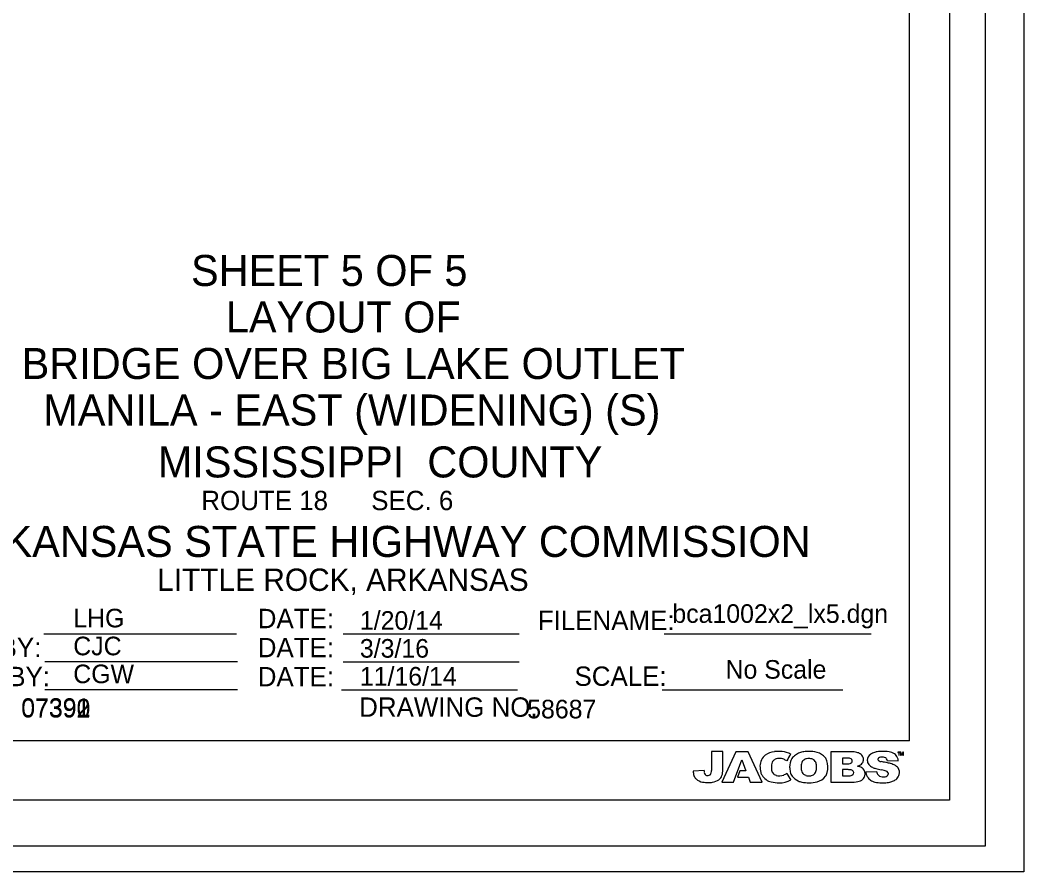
# Model space of a CAD drawing. Extents: x -290 to 969, y 225 to 885.
# Drawn here: x 549.6 to 743.9, y 225.4 to 390.2 of the extents above; entities that cross this region are included whole.
import ezdxf

# ---------------------------------------------------------------- set-up
doc = ezdxf.new("R2010")
doc.units = 0
for name, color, linetype in [('border', 7, 'Continuous'), ('Border 2660-Hwy18 - Level 62', 7, 'Continuous'), ('Border 2660-Hwy18 - Level 63', 7, 'Continuous'), ('Border 2660-Hwy18 - Text', 7, 'Continuous'), ('Border 2660-Hwy18 - Title Text', 7, 'Continuous'), ('Bridge No BLFR', 7, 'Continuous'), ('Bridge No BLO', 7, 'Continuous'), ('Bridge No Ditch 81', 7, 'Continuous'), ('Level 62 PDF', 7, 'Continuous'), ('Text', 7, 'Continuous'), ('Title Text', 7, 'Continuous')]:
    doc.layers.add(name, color=color, linetype=linetype)

msp = doc.modelspace()

# ---------------------------------------------------------------- linework, layer by layer
at = {"layer": 'border'}
for p, q in [((721.82, 250.72), (721.82, 867.08)), ((554.21, 271.46), (591.5, 271.46)), ((612.2, 271.42), (646.22, 271.42)), ((674.3, 271.42), (714.39, 271.42)), ((554.42, 266.06), (591.72, 266.06)), ((612.2, 266.02), (646.22, 266.02)), ((554.42, 260.66), (591.72, 260.66)), ((611.88, 260.62), (645.9, 260.62)), ((673.93, 260.62), (708.9, 260.62)), ((721.82, 250.72), (-238.51, 250.72))]:
    msp.add_line(p, q, dxfattribs=at)
for points in [[(685.67, 245.33), (685.67, 248.64), (683.45, 248.64), (683.45, 245.01)], [(689.35, 247.06), (690.13, 244.94), (688.97, 244.94), (688.49, 243.67), (690.6, 243.67), (690.95, 242.7), (693.27, 242.7), (690.59, 248.58), (688.16, 248.58), (685.47, 242.7), (687.74, 242.7), (689.35, 247.06)], [(710.84, 248.58), (706.58, 248.58), (706.58, 242.7)], [(709.79, 247.39), (708.81, 247.39), (708.81, 246.28)], [(717.53, 246.83), (719.63, 246.93)], [(719.98, 248.51), (719.53, 248.51), (719.53, 248.45), (719.71, 248.45), (719.71, 247.95), (719.79, 247.95), (719.79, 248.45), (719.98, 248.45), (719.98, 248.51)], [(720.12, 248.42), (720.12, 248.42), (720.3, 247.95), (720.35, 247.95), (720.54, 248.42), (720.54, 248.42), (720.54, 247.95), (720.61, 247.95), (720.61, 248.51), (720.51, 248.51), (720.33, 248.04), (720.14, 248.51), (720.05, 248.51), (720.05, 247.95), (720.12, 247.95), (720.12, 248.42)], [(682.02, 244.99), (679.9, 244.88)], [(708.81, 246.28), (709.84, 246.28)], [(709.94, 245.15), (708.81, 245.15), (708.81, 243.96)], [(708.81, 243.96), (709.95, 243.96)], [(715.46, 244.75), (713.36, 244.64)], [(706.58, 242.7), (710.41, 242.7)]]:
    msp.add_lwpolyline(points, dxfattribs=at)
for centre, radius, start, end in [((695.81, 245.79), 2.96, 155.2444, 178.6811), ((695.33, 246.02), 2.43, 126.8513, 155.2444), ((695.92, 245.23), 3.41, 94.7853, 126.8513), ((695.91, 246.33), 0.728, 134.3139, 161.2834), ((696.57, 245.66), 1.67, 110.7655, 134.3139), ((696.54, 237.78), 10.89, 86.903, 94.7853), ((696.54, 245.73), 1.59, 91.5073, 110.7655), ((696.59, 243.84), 3.48, 82.6359, 91.5073), ((696.85, 245.83), 1.48, 65.5548, 82.6359), ((696.95, 245.28), 3.38, 56.9246, 86.903), ((695.98, 243.93), 3.56, 54.6002, 65.5548), ((705.54, 243.32), 8.27, 144.635, 154.8844), ((701.6, 245.71), 3.01, 148.6249, 181.2859), ((700.96, 246.1), 2.26, 123.8806, 148.6249), ((702.08, 244.44), 4.26, 111.7104, 123.8806), ((701.71, 245.35), 3.28, 96.5371, 111.7104), ((701.77, 246.25), 0.861, 136.1177, 160.8611), ((702.27, 245.77), 1.55, 117.7176, 136.1177), ((702.65, 237.18), 11.51, 91.9058, 96.5371), ((702.08, 246.13), 1.15, 100.2108, 117.7176), ((702.35, 244.62), 2.68, 90.9675, 100.2108), ((702.48, 243.7), 4.98, 73.4477, 92.4253), ((702.32, 245.44), 1.87, 67.077, 90.4218), ((702.6, 246.09), 1.16, 24.6274, 67.077), ((702.94, 245.26), 3.36, 41.1934, 73.4477), ((704.16, 246.33), 1.74, 18.6966, 41.1934), ((702.1, 245.63), 3.91, 344.5708, 18.6966), ((709.74, 243.34), 4.05, 86.2098, 89.3498), ((709.91, 245.84), 1.54, 74.8723, 86.2098), ((710.16, 246.76), 0.588, 40.2425, 74.8723), ((710.36, 246.94), 0.324, 21.9604, 40.2425), ((710.12, 246.84), 0.584, 341.4625, 21.9604), ((710.85, 245.47), 3.11, 72.1885, 90.1477), ((711.24, 246.71), 1.81, 61.4844, 72.1885), ((711.3, 246.81), 1.69, 34.7868, 61.4844), ((711.91, 247.24), 0.944, 16.9455, 34.7868), ((711.94, 247.01), 0.922, 329.8182, 347.0949), ((711.51, 247.11), 1.37, 347.0949, 16.9455), ((715.05, 246.93), 1.43, 124.08, 177.6485), ((714.87, 246.94), 1.25, 177.6485, 218.8535), ((715.98, 245.55), 3.1, 108.2808, 124.08), ((715.78, 246.18), 2.43, 99.8173, 108.2808), ((716.6, 241.41), 7.27, 93.402, 99.8173), ((716.14, 247.07), 0.479, 146.4706, 165.3108), ((715.91, 247.13), 0.245, 165.3108, 208.2887), ((716.13, 247.28), 0.506, 211.7417, 226.6339), ((715.96, 247.19), 0.263, 130.7855, 146.4706), ((716.08, 247.23), 0.435, 226.6339, 245.1429), ((716.29, 246.81), 0.767, 97.3055, 130.7855), ((716.59, 248.33), 1.65, 245.1429, 260.9806), ((716.62, 241.06), 7.62, 80.6549, 93.402), ((716.45, 245.51), 2.08, 81.3212, 97.3055), ((716.6, 246.5), 1.08, 57.474, 81.3212), ((716.86, 246.9), 0.606, 37.1977, 57.474), ((716.5, 246.63), 1.05, 11.0051, 37.1977), ((717.42, 245.93), 2.69, 57.5906, 80.6549), ((718.07, 246.95), 1.48, 39.0736, 57.5906), ((717.79, 246.72), 1.84, 6.4385, 39.0736), ((683.56, 245.17), 3.68, 184.5698, 198.1069), ((683.83, 244.93), 1.81, 178.2556, 191.4961), ((681.07, 245.01), 2.38, 349.1575, 360), ((681.96, 245.21), 3.71, 351.3706, 1.8291), ((697.45, 245.76), 4.6, 178.6811, 194.3912), ((698.17, 245.57), 3.11, 161.2834, 178.6702), ((697.62, 245.58), 2.56, 178.6702, 195.8531), ((696.37, 245.22), 1.26, 195.8531, 214.5369), ((703.16, 245.75), 4.57, 181.2859, 193.1956), ((703.55, 245.63), 2.75, 160.8611, 181.2981), ((703.66, 245.64), 2.85, 181.2981, 197.9492), ((702.12, 245.87), 1.68, 2.7442, 24.6274), ((701.08, 245.6), 2.73, 342.4003, 0.0845), ((696.33, 245.6), 7.48, 0.0845, 2.7442), ((709.84, 248.18), 1.9, 270.0363, 284.1438), ((709.79, 237.74), 7.41, 86.6838, 88.8756), ((710.14, 243.66), 1.49, 75.9314, 86.6838), ((710.16, 246.91), 0.589, 284.1438, 307.8865), ((710.26, 244.15), 0.985, 59.6202, 75.9314), ((710.25, 246.79), 0.447, 307.8866, 341.4625), ((710.53, 244.61), 0.45, 30.8341, 59.6202), ((710.46, 244.57), 0.53, 337.5037, 30.8341), ((711.14, 248.02), 2.26, 284.6785, 296.8411), ((711.23, 243.11), 2.76, 61.0815, 79.9242), ((711.52, 247.26), 1.41, 296.8412, 329.8182), ((711.99, 244.51), 1.17, 44.9773, 61.0815), ((711.86, 244.38), 1.35, 342.9845, 44.9773), ((715.22, 247.22), 1.7, 218.8535, 233.6549), ((715.63, 247.78), 2.39, 233.6549, 244.7689), ((716.61, 249.85), 4.69, 244.7689, 253.473), ((718.04, 254.66), 9.7, 253.473, 259.8297), ((714.75, 236.35), 8.9, 76.0104, 79.8297), ((714.07, 232.5), 14.38, 77.5139, 80.9806), ((716.2, 242.15), 2.92, 67.9593, 76.0104), ((704.36, 188.63), 59.32, 76.8035, 77.5139), ((716.99, 244.12), 0.795, 39.9313, 67.9593), ((716.78, 241.62), 4.89, 65.6998, 76.8035), ((717.84, 243.95), 2.33, 51.3565, 65.6998), ((718.31, 244.55), 1.57, 36.5162, 51.3565), ((718.4, 244.61), 1.46, 345.1611, 36.5162), ((681.56, 244.51), 1.58, 198.1069, 225.9799), ((682.13, 245.1), 2.39, 225.9799, 261.0714), ((682.87, 244.73), 0.83, 191.4961, 218.7511), ((682.61, 244.52), 0.491, 218.7511, 257.488), ((682.73, 245.05), 1.03, 257.488, 275.7834), ((682.75, 244.79), 0.771, 275.7834, 301.6926), ((682.97, 244.44), 0.367, 301.6926, 325.4171), ((682.57, 244.72), 0.855, 325.4171, 349.1575), ((683.24, 245.47), 2.79, 279.1616, 305.8646), ((683.85, 244.63), 1.76, 305.8646, 338.7843), ((684.01, 244.56), 1.58, 338.7843, 350.0951), ((669.34, 247.13), 16.47, 350.0951, 351.3706), ((694.69, 245.05), 1.75, 194.3912, 214.1799), ((696.39, 246.2), 3.8, 214.1799, 231.6615), ((695.45, 245.02), 2.3, 231.6616, 258.686), ((696.29, 245.17), 1.16, 214.5369, 253.1918), ((696.62, 246.26), 2.31, 253.1918, 291.1956), ((696.66, 246.97), 4.37, 268.8163, 299.3878), ((696.45, 246.71), 2.78, 291.1956, 305.5144), ((708.96, 249.92), 12.2, 206.7197, 213.678), ((700.7, 245.17), 2.05, 193.1956, 217.7499), ((701.71, 245.96), 3.33, 217.7499, 244.1703), ((701.39, 245.28), 2.58, 244.1703, 259.4942), ((701.8, 245.03), 0.897, 197.9492, 222.7741), ((702.18, 245.39), 1.42, 222.7741, 250.1955), ((702.21, 245.48), 1.52, 250.1955, 269.1264), ((702.28, 249.7), 5.73, 269.1264, 272.0424), ((702.43, 245.5), 1.54, 272.0424, 299.5401), ((702.65, 245.1), 1.08, 299.5401, 342.4003), ((703.12, 245.7), 3.02, 285.9017, 322.6714), ((703.86, 245.14), 2.09, 322.6714, 344.5708), ((709.95, 247.08), 3.12, 270.0001, 276.6749), ((710.16, 245.26), 1.29, 276.6749, 293.0645), ((710.45, 244.57), 0.535, 293.0645, 337.5037), ((711.49, 244.64), 1.83, 279.6279, 313.6357), ((711.69, 244.43), 1.53, 313.6357, 342.9845), ((724.64, 246.23), 11.4, 187.9971, 189.0947), ((714.87, 244.67), 1.51, 189.0947, 202.464), ((715.92, 245.1), 2.64, 202.464, 215.8926), ((715.29, 244.64), 1.86, 215.8926, 243.2968), ((715.67, 245.4), 2.71, 243.2968, 257.4598), ((717.01, 244.99), 1.57, 188.5141, 201.638), ((716.44, 244.76), 0.957, 201.638, 242.3635), ((716.62, 245.11), 1.35, 242.3635, 264.6229), ((716.72, 246.17), 2.42, 264.6229, 273.901), ((716.79, 245.15), 1.39, 273.901, 289.1925), ((716.99, 244.58), 0.79, 289.1925, 322.566), ((717.27, 244.35), 0.434, 2.1813, 39.9313), ((717.28, 244.36), 0.422, 322.566, 2.1813), ((717.29, 245.92), 3.27, 282.5001, 295.6144), ((717.71, 245.06), 2.32, 295.6144, 314.022), ((718.05, 244.71), 1.82, 314.022, 345.1611), ((682.89, 249.97), 7.32, 261.0714, 269.9405), ((682.89, 247.66), 5.01, 269.9405, 279.1616), ((696.76, 251.54), 8.94, 258.686, 268.8163), ((702.56, 251.58), 8.98, 259.4942, 268.6426), ((702.47, 248), 5.4, 268.6426, 285.9017), ((710.1, 252.84), 10.14, 271.7224, 279.6279), ((716.47, 248.99), 6.39, 257.4598, 268.8656), ((716.69, 260.03), 17.43, 268.8656, 270.7612), ((716.85, 247.92), 5.32, 270.7612, 282.5001)]:
    msp.add_arc(centre, radius, start, end, dxfattribs=at)
at = {"layer": 'Border 2660-Hwy18 - Level 62'}
msp.add_lwpolyline([(-287.11, 884.65), (736.44, 884.65), (736.44, 230.36), (-287.11, 230.36)], close=True, dxfattribs=at)
at = {"layer": 'Border 2660-Hwy18 - Level 63'}
msp.add_lwpolyline([(-290.45, 880.36), (729.54, 880.36), (729.54, 239.27), (-290.45, 239.27)], close=True, dxfattribs=at)
at = {"layer": 'Level 62 PDF'}
msp.add_lwpolyline([(-279.61, 879.65), (743.94, 879.65), (743.94, 225.36), (-279.61, 225.36)], close=True, dxfattribs=at)

# ---------------------------------------------------------------- texts
at = {"layer": 'Border 2660-Hwy18 - Text'}
for s, p in [('DATE:', (595.64, 272.52)), ('FILENAME:', (649.85, 272.16)), ('CHECKED BY:', (519.76, 266.93)), ('DATE:', (595.64, 266.9)), ('DESIGNED BY:', (519.76, 261.3)), ('DATE:', (595.64, 261.27)), ('SCALE:', (656.95, 261.36)), ('DRAWING NO.', (615.27, 255.38))]:
    msp.add_text(s, height=3.75, dxfattribs=at).set_placement(p)
at = {"layer": 'Border 2660-Hwy18 - Title Text'}
for s, height, p in [('MISSISSIPPI  COUNTY', 6, (576.29, 301.69)), ('ROUTE 18      SEC. 6', 3.75, (584.72, 295.36)), ('ARKANSAS STATE HIGHWAY COMMISSION', 6, (535.48, 286.31)), ('LITTLE ROCK, ARKANSAS', 4.32, (576.17, 279.74))]:
    msp.add_text(s, height=height, dxfattribs=at).set_placement(p)
at = {"layer": 'Bridge No BLFR'}
msp.add_text('07392', height=3.6, dxfattribs=at).set_placement((549.86, 255.24))
at = {"layer": 'Bridge No BLO'}
msp.add_text('07391', height=3.6, dxfattribs=at).set_placement((549.86, 255.37))
at = {"layer": 'Bridge No Ditch 81'}
msp.add_text('07390', height=3.6, dxfattribs=at).set_placement((549.86, 255.24))
at = {"layer": 'Text'}
for s, p in [('LHG', (559.93, 272.68)), ('1/20/14', (615.41, 272.22)), ('bca1002x2_lx5.dgn', (675.89, 273.55)), ('CJC', (559.93, 267.28)), ('3/3/16', (615.41, 266.82)), ('No Scale', (686.18, 262.75)), ('CGW', (559.93, 261.88)), ('11/16/14', (615.41, 261.42)), ('58687', (647.79, 255.07))]:
    msp.add_text(s, height=3.6, dxfattribs=at).set_placement(p)
at = {"layer": 'Title Text'}
for s, p in [('SHEET 5 OF 5', (582.72, 338.74)), ('LAYOUT OF', (589.47, 329.74)), ('BRIDGE OVER BIG LAKE OUTLET', (549.94, 320.74)), ('MANILA - EAST (WIDENING) (S)', (554.12, 311.74))]:
    msp.add_text(s, height=6, dxfattribs=at).set_placement(p)

doc.saveas('drawing.dxf')
